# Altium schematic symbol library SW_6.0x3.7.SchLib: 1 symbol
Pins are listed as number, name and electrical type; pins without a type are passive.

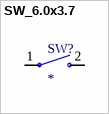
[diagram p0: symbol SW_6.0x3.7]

## SW_6.0x3.7
designator SW?
Switch Tactile OFF (ON) SPST Rectangular Button Gull Wing 0.05A 12VDC SMD Loose Piece; MP: 1437566-3
footprint SW_6.0x3.7
pins: 1, 2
